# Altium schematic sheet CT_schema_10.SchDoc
size 277 x 170 mm
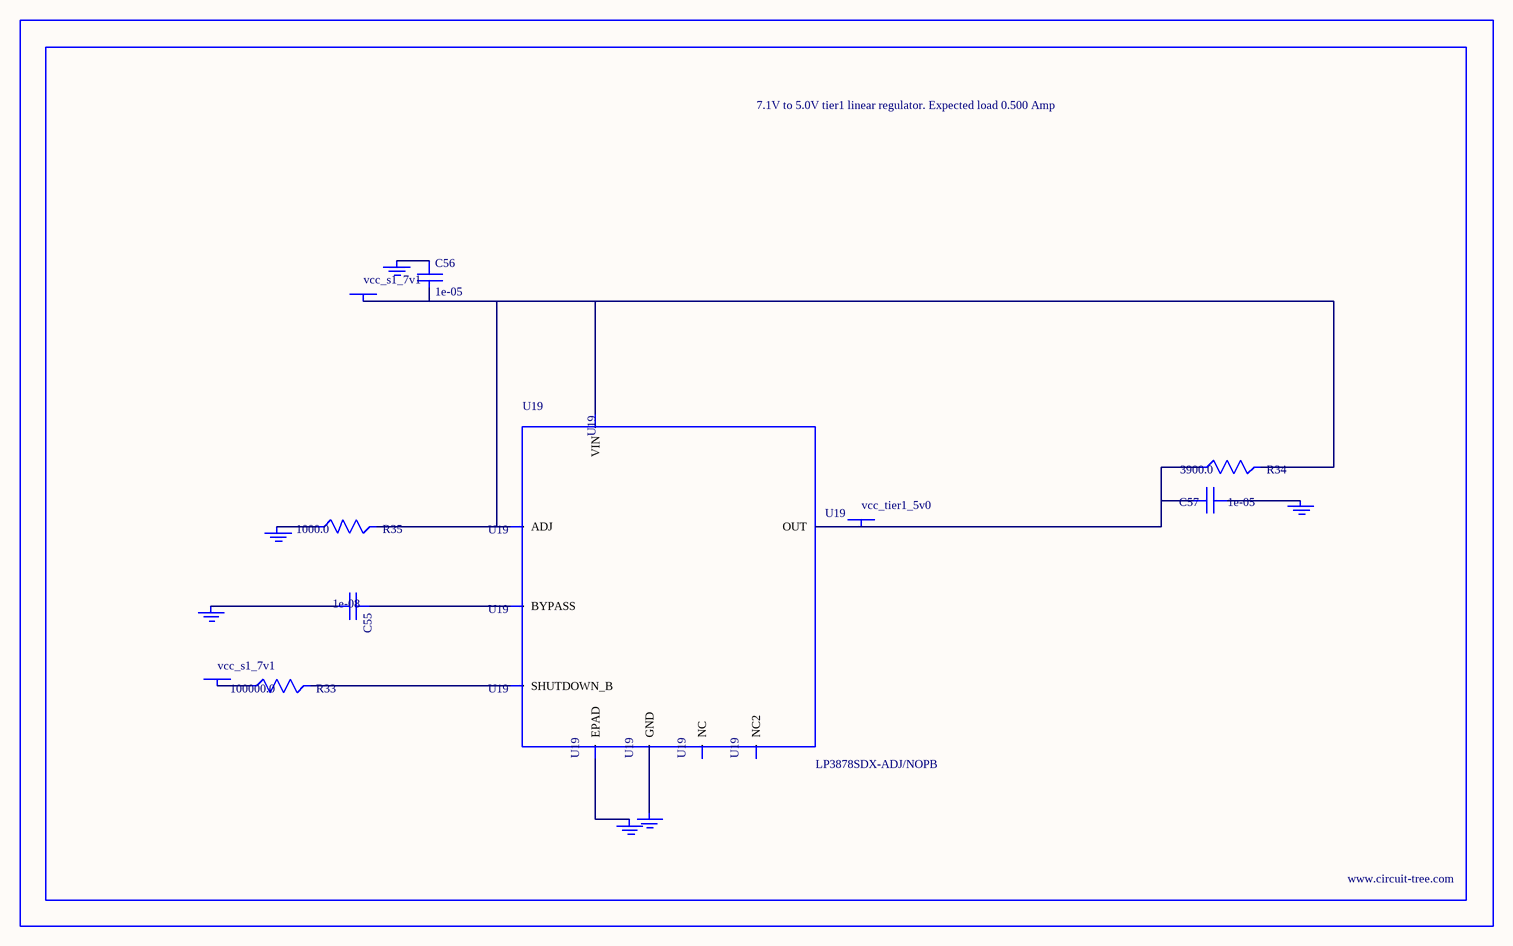
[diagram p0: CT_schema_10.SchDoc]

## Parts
BORDER9  (no value)
C55  1e-08  [C0402]
C56  1e-05  [C1206]
C57  1e-05  [C1210]
GND_INSTANCE_9_0  (no value)
GND_INSTANCE_9_1  (no value)
GND_INSTANCE_9_2  (no value)
GND_INSTANCE_9_3  (no value)
GND_INSTANCE_9_4  (no value)
GND_INSTANCE_9_5  (no value)
POWER_INSTANCE_9_0  vcc_s1_7v1
POWER_INSTANCE_9_1  vcc_s1_7v1
POWER_INSTANCE_9_2  vcc_tier1_5v0
R33  100000.0  [R0603]
R34  3900.0  [R0603]
R35  1000.0  [R0603]
U19  LP3878SDX-ADJ/NOPB  [WSON-8]

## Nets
NetC55_1: C55.1 U19.1(BYPASS)
NetC55_2: C55.2 GND_INSTANCE_9_0.0(GND)
NetC56_1: C56.1 GND_INSTANCE_9_1.0(GND)
NetC56_2: C56.2 POWER_INSTANCE_9_0.0(PWR) R34.2 R35.2 U19.4(VIN) U19.6(ADJ)
NetC57_1: C57.1 GND_INSTANCE_9_2.0(GND)
NetC57_2: C57.2 POWER_INSTANCE_9_2.0(PWR) R34.1 U19.5(OUT)
NetGND_INSTANCE_9_3_0: GND_INSTANCE_9_3.0(GND) R35.1
NetGND_INSTANCE_9_4_0: GND_INSTANCE_9_4.0(GND) U19.PAD(EPAD)
NetGND_INSTANCE_9_5_0: GND_INSTANCE_9_5.0(GND) U19.3(GND)
NetPOWER_INSTANCE_9_1_0: POWER_INSTANCE_9_1.0(PWR) R33.1
NetR33_2: R33.2 U19.8(SHUTDOWN_B)

Not connected (* = marked no-connect by the designer): U19 2(NC) 7(NC2)

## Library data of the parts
BORDER9 = BORDER_PAGE9
C55 = C0402C103K3RAC
C56 = C1206C106K3RACTU
C57 = GRM32DR61E106MA12L
GND_INSTANCE_9_0-GND_INSTANCE_9_5 = GND
POWER_INSTANCE_9_0-POWER_INSTANCE_9_2 = PWR
R33 = RC0603JR-07100KL
R34 = RC0603JR-073K9L
R35 = RC0603JR-071KL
